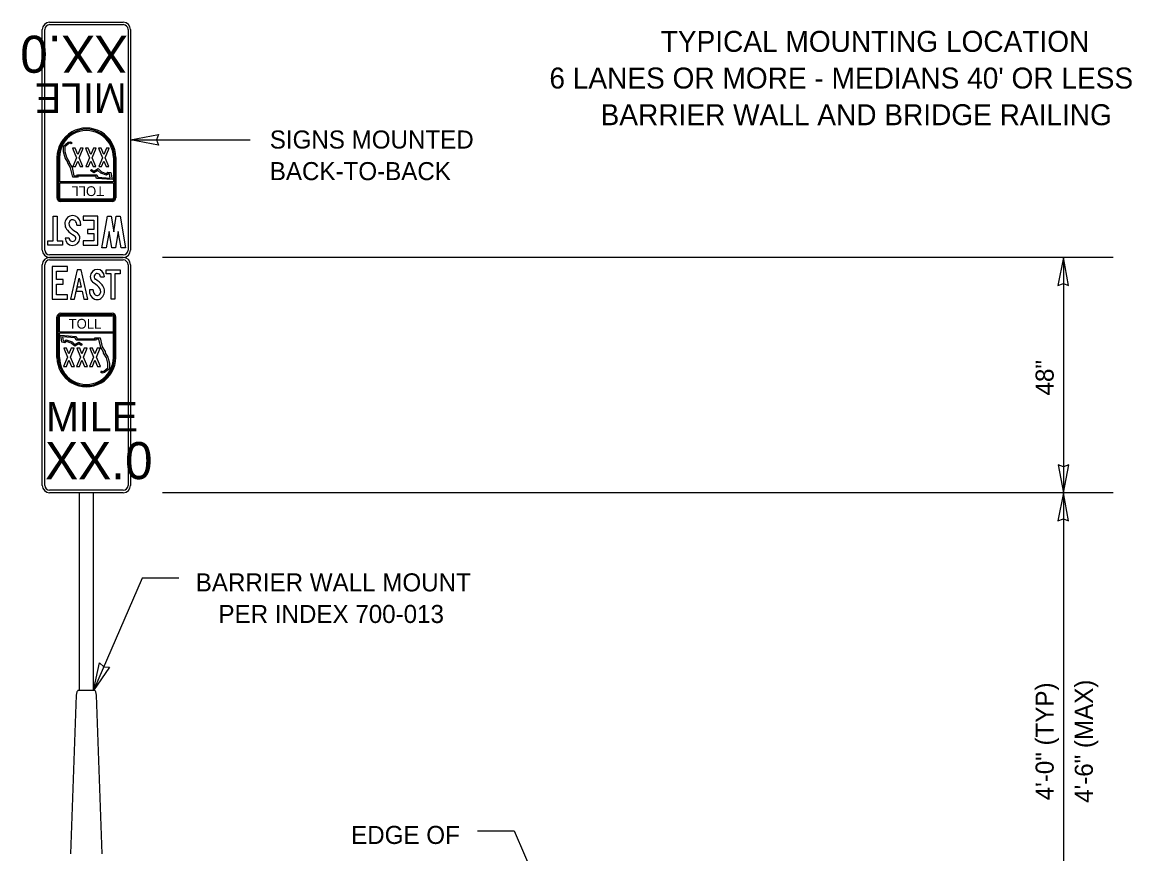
# Model space of a CAD drawing. Extents: x 57428 to 58066, y 11696 to 12105.
# Drawn here: x 57750 to 57922.1, y 11796.7 to 11925.7 of the extents above; entities that cross this region are included whole.
import ezdxf

# ---------------------------------------------------------------- set-up
doc = ezdxf.new("R2010")
doc.units = 0
for name, color, linetype in [('DimLines_dp', 7, 'Continuous'), ('NonPlottingEle_dp', 7, 'Continuous'), ('SignPanel', 7, 'Continuous'), ('TextTables', 7, 'Continuous'), ('XSGrdLine_ex', 7, 'Continuous')]:
    doc.layers.add(name, color=color, linetype=linetype)

msp = doc.modelspace()

# ---------------------------------------------------------------- linework, layer by layer
at = {"layer": 'DimLines_dp'}
for p, q in [((57766.83, 11907.47), (57771.18, 11908.31)), ((57771.18, 11908.31), (57770.85, 11907.47)), ((57766.83, 11907.47), (57785.36, 11907.47)), ((57771.18, 11906.66), (57766.83, 11907.47)), ((57770.85, 11907.47), (57771.18, 11906.66)), ((57919.19, 11889.21), (57771.8, 11889.21)), ((57911.45, 11889.21), (57910.61, 11884.86)), ((57911.45, 11889.21), (57911.45, 11852.71)), ((57912.26, 11884.86), (57911.45, 11889.21)), ((57910.61, 11884.86), (57911.45, 11885.19)), ((57911.45, 11885.19), (57912.26, 11884.86)), ((57911.45, 11858.7), (57911.45, 11772.84)), ((57911.45, 11856.73), (57910.64, 11857.06)), ((57910.64, 11857.06), (57911.45, 11852.71)), ((57911.45, 11856.73), (57910.64, 11857.06)), ((57910.64, 11857.06), (57911.45, 11852.71)), ((57911.45, 11852.71), (57912.29, 11857.06)), ((57912.29, 11857.06), (57911.45, 11856.73)), ((57911.45, 11852.71), (57912.29, 11857.06)), ((57912.29, 11857.06), (57911.45, 11856.73)), ((57919.19, 11852.71), (57771.8, 11852.71)), ((57911.45, 11852.71), (57910.61, 11848.36)), ((57912.26, 11848.36), (57911.45, 11852.71)), ((57910.61, 11848.36), (57911.45, 11848.69)), ((57911.45, 11848.69), (57912.26, 11848.36)), ((57768.66, 11839.46), (57761.07, 11822.02)), ((57774.31, 11839.46), (57768.66, 11839.46)), ((57761.07, 11822.02), (57762.04, 11826.34)), ((57763.55, 11825.68), (57761.07, 11822.02)), ((57762.04, 11826.34), (57762.68, 11825.7)), ((57762.68, 11825.7), (57763.55, 11825.68)), ((57820.64, 11800.28), (57826.29, 11800.28)), ((57826.29, 11800.28), (57839.61, 11769.66))]:
    msp.add_line(p, q, dxfattribs=at)
at = {"layer": 'NonPlottingEle_dp'}
for p, q in [((57758.91, 11822.02), (57758.91, 11852.73)), ((57761.07, 11822.02), (57761.07, 11852.73))]:
    msp.add_line(p, q, dxfattribs=at)
at = {"layer": 'SignPanel'}
for p, q in [((57756.43, 11906.48), (57757.18, 11907.09)), ((57756.43, 11905.62), (57756.43, 11906.48)), ((57757.29, 11906.88), (57756.66, 11906.37)), ((57756.66, 11906.37), (57756.66, 11905.65)), ((57757.18, 11907.09), (57757.54, 11907.18)), ((57757.49, 11906.93), (57757.29, 11906.88)), ((57757.63, 11906.83), (57757.49, 11906.93)), ((57757.54, 11907.18), (57757.77, 11907.02)), ((57757.77, 11907.02), (57757.63, 11906.83)), ((57755.43, 11904.74), (57755.43, 11898.46)), ((57755.62, 11904.74), (57755.62, 11898.46)), ((57755.81, 11904.74), (57755.81, 11900.94)), ((57756.68, 11904.69), (57756.43, 11905.62)), ((57756.66, 11905.65), (57756.9, 11904.78)), ((57757.09, 11904.02), (57756.68, 11904.69)), ((57756.9, 11904.78), (57757.32, 11904.08)), ((57764.17, 11904.74), (57764.17, 11900.94)), ((57764.36, 11904.74), (57764.36, 11898.46)), ((57764.55, 11904.74), (57764.55, 11898.46)), ((57757.09, 11903.83), (57757.09, 11904.02)), ((57757.54, 11903.11), (57757.09, 11903.83)), ((57757.32, 11904.08), (57757.32, 11903.9)), ((57757.32, 11903.9), (57757.76, 11903.2)), ((57757.88, 11901.68), (57757.54, 11903.11)), ((57757.76, 11903.2), (57758.06, 11901.91)), ((57760.65, 11902.69), (57760.78, 11902.88)), ((57760.78, 11902.88), (57761.16, 11902.62)), ((57761.16, 11902.62), (57761.79, 11903)), ((57761.79, 11903), (57762.33, 11902.5)), ((57758.61, 11901.68), (57757.88, 11901.68)), ((57758.06, 11901.91), (57758.49, 11901.91)), ((57758.49, 11901.91), (57758.59, 11902.06)), ((57758.59, 11902.06), (57761.6, 11902.06)), ((57758.71, 11901.83), (57758.61, 11901.68)), ((57761.45, 11901.83), (57758.71, 11901.83)), ((57761.15, 11902.35), (57760.65, 11902.69)), ((57761.76, 11902.71), (57761.15, 11902.35)), ((57761.58, 11901.49), (57761.45, 11901.83)), ((57763.96, 11901.3), (57761.58, 11901.49)), ((57761.6, 11902.06), (57761.74, 11901.7)), ((57761.74, 11901.7), (57763.69, 11901.55)), ((57762.21, 11902.29), (57761.76, 11902.71)), ((57763.13, 11902), (57762.21, 11902.29)), ((57762.33, 11902.5), (57763.08, 11902.25)), ((57762.7, 11901.64), (57762.7, 11901.64)), ((57763.08, 11902.25), (57763.33, 11902.45)), ((57763.4, 11902.21), (57763.13, 11902)), ((57763.33, 11902.45), (57763.79, 11902.39)), ((57763.59, 11902.18), (57763.4, 11902.21)), ((57763.69, 11901.55), (57763.59, 11902.18)), ((57763.79, 11902.39), (57763.96, 11901.3)), ((57764.17, 11900.94), (57755.81, 11900.94)), ((57755.81, 11900.74), (57755.81, 11898.46)), ((57764.17, 11900.74), (57755.81, 11900.74)), ((57764.17, 11900.74), (57764.17, 11898.46)), ((57763.98, 11898.28), (57756, 11898.28)), ((57763.98, 11898.08), (57756, 11898.08)), ((57763.98, 11897.89), (57756, 11897.89)), ((57758.49, 11894.24), (57759.12, 11894.24)), ((57758.49, 11894.24), (57759.12, 11894.24)), ((57758.49, 11894.24), (57759.12, 11894.24)), ((57757.3, 11892.23), (57756.68, 11892.23)), ((57757.3, 11892.23), (57756.68, 11892.23)), ((57757.3, 11892.23), (57756.68, 11892.23)), ((57762.18, 11886.22), (57762.77, 11886.22)), ((57762.18, 11886.22), (57762.77, 11886.22)), ((57762.18, 11886.22), (57762.77, 11886.22)), ((57761.05, 11884.18), (57760.45, 11884.18)), ((57761.05, 11884.18), (57760.45, 11884.18)), ((57761.05, 11884.18), (57760.45, 11884.18)), ((57756, 11880.56), (57763.98, 11880.56)), ((57755.43, 11873.71), (57755.43, 11879.99)), ((57755.62, 11873.71), (57755.62, 11879.99)), ((57755.81, 11877.71), (57755.81, 11879.99)), ((57756, 11880.37), (57763.98, 11880.37)), ((57756, 11880.17), (57763.98, 11880.17)), ((57764.17, 11877.71), (57764.17, 11879.99)), ((57764.36, 11873.71), (57764.36, 11879.99)), ((57764.55, 11873.71), (57764.55, 11879.99)), ((57755.81, 11877.71), (57764.17, 11877.71)), ((57755.81, 11873.71), (57755.81, 11877.52)), ((57755.81, 11877.52), (57764.17, 11877.52)), ((57756.19, 11876.06), (57756.02, 11877.15)), ((57756.02, 11877.15), (57758.4, 11876.96)), ((57764.17, 11873.71), (57764.17, 11877.52)), ((57756.65, 11876), (57756.19, 11876.06)), ((57758.24, 11876.75), (57756.29, 11876.9)), ((57756.29, 11876.9), (57756.39, 11876.27)), ((57756.39, 11876.27), (57756.58, 11876.24)), ((57756.58, 11876.24), (57756.85, 11876.46)), ((57756.9, 11876.2), (57756.65, 11876)), ((57756.85, 11876.46), (57757.77, 11876.16)), ((57757.65, 11875.95), (57756.9, 11876.2)), ((57757.28, 11876.81), (57757.28, 11876.81)), ((57758.19, 11875.45), (57757.65, 11875.95)), ((57757.77, 11876.16), (57758.22, 11875.74)), ((57758.82, 11875.83), (57758.19, 11875.45)), ((57758.22, 11875.74), (57758.83, 11876.1)), ((57758.38, 11876.39), (57758.24, 11876.75)), ((57761.39, 11876.39), (57758.38, 11876.39)), ((57758.4, 11876.96), (57758.54, 11876.62)), ((57758.54, 11876.62), (57761.27, 11876.62)), ((57759.2, 11875.57), (57758.82, 11875.83)), ((57758.83, 11876.1), (57759.33, 11875.76)), ((57759.33, 11875.76), (57759.2, 11875.57)), ((57761.27, 11876.62), (57761.37, 11876.77)), ((57761.37, 11876.77), (57762.1, 11876.77)), ((57761.49, 11876.54), (57761.39, 11876.39)), ((57761.92, 11876.54), (57761.49, 11876.54)), ((57762.22, 11875.25), (57761.92, 11876.54)), ((57762.1, 11876.77), (57762.44, 11875.34)), ((57762.44, 11875.34), (57762.89, 11874.62)), ((57762.66, 11874.55), (57762.22, 11875.25)), ((57762.66, 11874.37), (57762.66, 11874.55)), ((57763.09, 11873.67), (57762.66, 11874.37)), ((57762.89, 11874.62), (57762.89, 11874.43)), ((57762.89, 11874.43), (57763.3, 11873.76)), ((57763.32, 11872.8), (57763.09, 11873.67)), ((57763.3, 11873.76), (57763.55, 11872.84)), ((57762.69, 11871.57), (57763.32, 11872.08)), ((57763.55, 11871.97), (57762.8, 11871.36)), ((57763.32, 11872.08), (57763.32, 11872.8)), ((57763.55, 11872.84), (57763.55, 11871.97)), ((57762.22, 11871.43), (57762.35, 11871.62)), ((57762.44, 11871.27), (57762.22, 11871.43)), ((57762.35, 11871.62), (57762.49, 11871.52)), ((57762.8, 11871.36), (57762.44, 11871.27)), ((57762.49, 11871.52), (57762.69, 11871.57))]:
    msp.add_line(p, q, dxfattribs=at)
for points in [[(57754.29, 11925.72), (57765.69, 11925.72)], [(57754.29, 11925.34), (57765.69, 11925.34)], [(57753.15, 11890.37), (57753.15, 11924.58)], [(57753.53, 11890.37), (57753.53, 11924.58)], [(57766.45, 11924.58), (57766.45, 11890.37)], [(57766.83, 11924.58), (57766.83, 11890.37)], [(57765.69, 11889.61), (57754.29, 11889.61)], [(57765.69, 11889.23), (57754.29, 11889.23)], [(57754.29, 11889.23), (57765.69, 11889.23)], [(57753.15, 11853.87), (57753.15, 11888.08)], [(57753.53, 11853.87), (57753.53, 11888.08)], [(57754.29, 11888.85), (57765.69, 11888.85)], [(57766.45, 11888.08), (57766.45, 11853.87)], [(57766.83, 11888.08), (57766.83, 11853.87)], [(57765.69, 11853.11), (57754.29, 11853.11)], [(57765.69, 11852.73), (57754.29, 11852.73)]]:
    msp.add_lwpolyline(points, dxfattribs=at)
for points in [[(57759.07, 11906.16), (57758.66, 11905.18), (57758.25, 11906.16), (57757.83, 11906.16), (57758.45, 11904.67), (57757.88, 11903.31), (57758.3, 11903.31), (57758.66, 11904.16), (57759.02, 11903.31), (57759.45, 11903.31), (57758.87, 11904.67), (57759.5, 11906.16)], [(57761.09, 11906.16), (57760.68, 11905.18), (57760.27, 11906.16), (57759.84, 11906.16), (57760.46, 11904.67), (57759.89, 11903.31), (57760.32, 11903.31), (57760.68, 11904.16), (57761.04, 11903.31), (57761.46, 11903.31), (57760.89, 11904.67), (57761.51, 11906.16)], [(57763.1, 11906.16), (57762.69, 11905.18), (57762.28, 11906.16), (57761.86, 11906.16), (57762.48, 11904.67), (57761.91, 11903.31), (57762.33, 11903.31), (57762.69, 11904.16), (57763.05, 11903.31), (57763.48, 11903.31), (57762.91, 11904.67), (57763.53, 11906.16)], [(57755.44, 11891.78), (57756.26, 11891.78), (57756.26, 11891.15), (57753.99, 11891.15), (57753.99, 11891.78), (57754.82, 11891.78), (57754.82, 11895.65), (57755.44, 11895.65)], [(57755.44, 11891.78), (57756.26, 11891.78), (57756.26, 11891.15), (57753.99, 11891.15), (57753.99, 11891.78), (57754.82, 11891.78), (57754.82, 11895.65), (57755.44, 11895.65)], [(57755.44, 11891.78), (57756.26, 11891.78), (57756.26, 11891.15), (57753.99, 11891.15), (57753.99, 11891.78), (57754.82, 11891.78), (57754.82, 11895.65), (57755.44, 11895.65)], [(57761.14, 11895.02), (57761.14, 11893.58), (57760.17, 11893.58), (57760.17, 11892.95), (57761.14, 11892.95), (57761.14, 11891.78), (57759.5, 11891.78), (57759.5, 11891.15), (57761.76, 11891.15), (57761.76, 11895.65), (57759.5, 11895.65), (57759.5, 11895.02)], [(57761.14, 11895.02), (57761.14, 11893.58), (57760.17, 11893.58), (57760.17, 11892.95), (57761.14, 11892.95), (57761.14, 11891.78), (57759.5, 11891.78), (57759.5, 11891.15), (57761.76, 11891.15), (57761.76, 11895.65), (57759.5, 11895.65), (57759.5, 11895.02)], [(57761.14, 11895.02), (57761.14, 11893.58), (57760.17, 11893.58), (57760.17, 11892.95), (57761.14, 11892.95), (57761.14, 11891.78), (57759.5, 11891.78), (57759.5, 11891.15), (57761.76, 11891.15), (57761.76, 11895.65), (57759.5, 11895.65), (57759.5, 11895.02)], [(57764.93, 11893.26), (57764.52, 11890.7), (57763.92, 11890.7), (57763.51, 11893.26), (57763.06, 11890.7), (57762.37, 11890.7), (57763.24, 11895.65), (57763.83, 11895.65), (57764.22, 11893.18), (57764.61, 11895.65), (57765.2, 11895.65), (57766.07, 11890.7), (57765.38, 11890.7)], [(57764.93, 11893.26), (57764.52, 11890.7), (57763.92, 11890.7), (57763.51, 11893.26), (57763.06, 11890.7), (57762.37, 11890.7), (57763.24, 11895.65), (57763.83, 11895.65), (57764.22, 11893.18), (57764.61, 11895.65), (57765.2, 11895.65), (57766.07, 11890.7), (57765.38, 11890.7)], [(57764.93, 11893.26), (57764.52, 11890.7), (57763.92, 11890.7), (57763.51, 11893.26), (57763.06, 11890.7), (57762.37, 11890.7), (57763.24, 11895.65), (57763.83, 11895.65), (57764.22, 11893.18), (57764.61, 11895.65), (57765.2, 11895.65), (57766.07, 11890.7), (57765.38, 11890.7)], [(57755.35, 11883.45), (57755.35, 11885.07), (57756.37, 11885.07), (57756.37, 11885.78), (57755.35, 11885.78), (57755.35, 11887.1), (57757.07, 11887.1), (57757.07, 11887.81), (57754.7, 11887.81), (57754.7, 11882.74), (57757.07, 11882.74), (57757.07, 11883.45)], [(57755.35, 11883.45), (57755.35, 11885.07), (57756.37, 11885.07), (57756.37, 11885.78), (57755.35, 11885.78), (57755.35, 11887.1), (57757.07, 11887.1), (57757.07, 11887.81), (57754.7, 11887.81), (57754.7, 11882.74), (57757.07, 11882.74), (57757.07, 11883.45)], [(57755.35, 11883.45), (57755.35, 11885.07), (57756.37, 11885.07), (57756.37, 11885.78), (57755.35, 11885.78), (57755.35, 11887.1), (57757.07, 11887.1), (57757.07, 11887.81), (57754.7, 11887.81), (57754.7, 11882.74), (57757.07, 11882.74), (57757.07, 11883.45)], [(57759.32, 11883.97), (57759.59, 11882.74), (57760.2, 11882.74), (57759.18, 11887.32), (57758.55, 11887.32), (57757.53, 11882.74), (57758.13, 11882.74), (57758.41, 11883.97)], [(57758.55, 11884.61), (57758.41, 11883.97), (57759.32, 11883.97), (57759.59, 11882.74), (57760.2, 11882.74), (57759.18, 11887.32), (57758.55, 11887.32), (57757.53, 11882.74), (57758.13, 11882.74), (57758.86, 11886.02), (57759.18, 11884.61)], [(57758.55, 11884.61), (57758.41, 11883.97), (57759.32, 11883.97), (57759.59, 11882.74), (57760.2, 11882.74), (57759.18, 11887.32), (57758.55, 11887.32), (57757.53, 11882.74), (57758.13, 11882.74), (57758.86, 11886.02), (57759.18, 11884.61)], [(57763.83, 11886.68), (57763.05, 11886.68), (57763.05, 11887.32), (57765.2, 11887.32), (57765.2, 11886.68), (57764.42, 11886.68), (57764.42, 11882.74), (57763.83, 11882.74)], [(57763.83, 11886.68), (57763.05, 11886.68), (57763.05, 11887.32), (57765.2, 11887.32), (57765.2, 11886.68), (57764.42, 11886.68), (57764.42, 11882.74), (57763.83, 11882.74)], [(57763.83, 11886.68), (57763.05, 11886.68), (57763.05, 11887.32), (57765.2, 11887.32), (57765.2, 11886.68), (57764.42, 11886.68), (57764.42, 11882.74), (57763.83, 11882.74)], [(57758.86, 11886.02), (57759.18, 11884.61), (57758.55, 11884.61)], [(57756.88, 11872.29), (57757.29, 11873.27), (57757.7, 11872.29), (57758.12, 11872.29), (57757.5, 11873.78), (57758.07, 11875.14), (57757.65, 11875.14), (57757.29, 11874.29), (57756.93, 11875.14), (57756.5, 11875.14), (57757.07, 11873.78), (57756.45, 11872.29)], [(57758.9, 11872.29), (57759.3, 11873.27), (57759.71, 11872.29), (57760.14, 11872.29), (57759.52, 11873.78), (57760.09, 11875.14), (57759.66, 11875.14), (57759.3, 11874.29), (57758.95, 11875.14), (57758.52, 11875.14), (57759.09, 11873.78), (57758.47, 11872.29)], [(57760.91, 11872.29), (57761.32, 11873.27), (57761.73, 11872.29), (57762.16, 11872.29), (57761.53, 11873.78), (57762.11, 11875.14), (57761.68, 11875.14), (57761.32, 11874.29), (57760.96, 11875.14), (57760.53, 11875.14), (57761.11, 11873.78), (57760.48, 11872.29)]]:
    msp.add_lwpolyline(points, close=True, dxfattribs=at)
for centre, radius, start, end in [((57754.29, 11924.58), 1.14, 90, 180), ((57754.29, 11924.58), 0.76, 90, 180), ((57765.69, 11924.58), 1.14, 360, 90), ((57765.69, 11924.58), 0.76, 360, 90), ((57754.29, 11890.37), 1.14, 180, 270), ((57754.29, 11888.08), 1.14, 90, 180), ((57754.29, 11890.37), 0.76, 180, 270), ((57765.69, 11890.37), 1.14, 270, 360), ((57765.69, 11890.37), 0.76, 270, 360), ((57765.69, 11888.08), 1.14, 0, 90), ((57754.29, 11888.08), 0.76, 90, 180), ((57765.69, 11888.08), 0.76, 0, 90), ((57754.29, 11853.87), 1.14, 180, 270), ((57754.29, 11853.87), 0.76, 180, 270), ((57765.69, 11853.87), 1.14, 270, 360), ((57765.69, 11853.87), 0.76, 270, 360)]:
    msp.add_arc(centre, radius, start, end, dxfattribs=at)
for centre, major_axis, ratio, start_param, end_param in [((57759.99, 11904.74), (0, 4.56), 0.9997, 4.712389, 7.853982), ((57759.99, 11904.74), (0, 4.37), 0.9997, 4.712389, 7.853982), ((57759.99, 11904.74), (0, 4.18), 0.9997, 4.712389, 7.853982), ((57756, 11898.47), (0, -0.57), 0.9997, 4.712389, 6.283185), ((57756, 11898.47), (0, -0.38), 0.9997, 4.712389, 6.283185), ((57756, 11898.47), (0, -0.19), 0.9997, 4.712389, 6.283185), ((57763.98, 11898.47), (0, -0.38), 0.9997, 0, 1.570796), ((57763.98, 11898.47), (0, -0.19), 0.9997, 0, 1.570796), ((57763.98, 11898.47), (0, -0.57), 0.9997, 0, 1.570796), ((57758.03, 11894.43), (0, -1.4), 0.981197, 4.260987, 5.485755), ((57758.03, 11894.43), (0, -1.4), 0.981197, 4.260987, 5.485755), ((57758.03, 11894.43), (0, -1.4), 0.981197, 4.260987, 5.485755), ((57757.87, 11894.49), (0, -1.23), 0.981197, 2.786047, 4.251692), ((57757.87, 11894.49), (0, -1.23), 0.981197, 2.786047, 4.251692), ((57757.87, 11894.49), (0, -1.23), 0.981197, 2.786047, 4.251692), ((57758.04, 11894.42), (0, -0.78), 0.981197, 4.254409, 5.632398), ((57758.04, 11894.42), (0, -0.78), 0.981197, 4.254409, 5.632398), ((57758.04, 11894.42), (0, -0.78), 0.981197, 4.254409, 5.632398), ((57757.85, 11894.5), (0, -0.572), 0.981197, 2.261787, 4.23006), ((57757.85, 11894.5), (0, -0.572), 0.981197, 2.261787, 4.23006), ((57757.85, 11894.5), (0, -0.572), 0.981197, 2.261787, 4.23006), ((57757.61, 11894.28), (0, -0.897), 0.981197, 1.524757, 2.28214), ((57757.61, 11894.28), (0, -0.897), 0.981197, 1.524757, 2.28214), ((57757.61, 11894.28), (0, -0.897), 0.981197, 1.524757, 2.28214), ((57757.67, 11894.31), (0, -1.47), 0.981197, 1.526364, 2.701682), ((57757.67, 11894.31), (0, -1.47), 0.981197, 1.526364, 2.701682), ((57757.67, 11894.31), (0, -1.47), 0.981197, 1.526364, 2.701682), ((57760.15, 11896.4), (0, -4.32), 0.981197, 5.462886, 5.782242), ((57760.15, 11896.4), (0, -4.32), 0.981197, 5.462886, 5.782242), ((57760.15, 11896.4), (0, -4.32), 0.981197, 5.462886, 5.782242), ((57760.68, 11897.09), (0, -4.56), 0.981197, 5.515137, 5.786988), ((57760.68, 11897.09), (0, -4.56), 0.981197, 5.515137, 5.786988), ((57760.68, 11897.09), (0, -4.56), 0.981197, 5.515137, 5.786988), ((57757.9, 11892.21), (0, -0.453), 0.981197, 0.87378, 2.656959), ((57757.9, 11892.21), (0, -0.453), 0.981197, 0.87378, 2.656959), ((57757.9, 11892.21), (0, -0.453), 0.981197, 0.87378, 2.656959), ((57757.94, 11892.23), (0, -1.05), 0.981197, 1.534831, 2.511766), ((57757.94, 11892.23), (0, -1.05), 0.981197, 1.534831, 2.511766), ((57757.94, 11892.23), (0, -1.05), 0.981197, 1.534831, 2.511766), ((57757.83, 11892.26), (0, -1.17), 0.981197, 4.736267, 7.790596), ((57757.83, 11892.26), (0, -1.17), 0.981197, 4.736267, 7.790596), ((57757.83, 11892.26), (0, -1.17), 0.981197, 4.736267, 7.790596), ((57757.84, 11892.27), (0, -0.55), 0.981197, 4.786904, 7.140738), ((57757.84, 11892.27), (0, -0.55), 0.981197, 4.786904, 7.140738), ((57757.84, 11892.27), (0, -0.55), 0.981197, 4.786904, 7.140738), ((57761.68, 11886.19), (0, 1.19), 0.91923, 4.736267, 7.790596), ((57761.68, 11886.19), (0, 1.19), 0.91923, 4.736267, 7.790596), ((57761.68, 11886.19), (0, 1.19), 0.91923, 4.736267, 7.790596), ((57761.57, 11886.23), (0, 1.07), 0.91923, 1.534831, 2.511766), ((57761.57, 11886.23), (0, 1.07), 0.91923, 1.534831, 2.511766), ((57761.57, 11886.23), (0, 1.07), 0.91923, 1.534831, 2.511766), ((57761.61, 11886.25), (0, 0.46), 0.91923, 0.87378, 2.656959), ((57761.61, 11886.25), (0, 0.46), 0.91923, 0.87378, 2.656959), ((57761.61, 11886.25), (0, 0.46), 0.91923, 0.87378, 2.656959), ((57761.67, 11886.18), (0, 0.558), 0.91923, 4.786904, 7.140738), ((57761.67, 11886.18), (0, 0.558), 0.91923, 4.786904, 7.140738), ((57761.67, 11886.18), (0, 0.558), 0.91923, 4.786904, 7.140738), ((57759.47, 11881.99), (0, 4.39), 0.91923, 5.462886, 5.782242), ((57759.47, 11881.99), (0, 4.39), 0.91923, 5.462886, 5.782242), ((57759.47, 11881.99), (0, 4.39), 0.91923, 5.462886, 5.782242), ((57761.83, 11884.11), (0, 1.5), 0.91923, 1.526364, 2.701682), ((57761.83, 11884.11), (0, 1.5), 0.91923, 1.526364, 2.701682), ((57761.83, 11884.11), (0, 1.5), 0.91923, 1.526364, 2.701682), ((57758.96, 11881.29), (0, 4.63), 0.91923, 5.515137, 5.786988), ((57758.96, 11881.29), (0, 4.63), 0.91923, 5.515137, 5.786988), ((57758.96, 11881.29), (0, 4.63), 0.91923, 5.515137, 5.786988), ((57761.88, 11884.14), (0, 0.911), 0.91923, 1.524757, 2.28214), ((57761.88, 11884.14), (0, 0.911), 0.91923, 1.524757, 2.28214), ((57761.88, 11884.14), (0, 0.911), 0.91923, 1.524757, 2.28214), ((57761.48, 11883.99), (0, 0.792), 0.91923, 4.254409, 5.632398), ((57761.48, 11883.99), (0, 0.792), 0.91923, 4.254409, 5.632398), ((57761.48, 11883.99), (0, 0.792), 0.91923, 4.254409, 5.632398), ((57761.49, 11883.99), (0, 1.42), 0.91923, 4.260987, 5.485755), ((57761.49, 11883.99), (0, 1.42), 0.91923, 4.260987, 5.485755), ((57761.49, 11883.99), (0, 1.42), 0.91923, 4.260987, 5.485755), ((57761.64, 11883.93), (0, 1.24), 0.91923, 2.786047, 4.251692), ((57761.64, 11883.93), (0, 1.24), 0.91923, 2.786047, 4.251692), ((57761.64, 11883.93), (0, 1.24), 0.91923, 2.786047, 4.251692), ((57761.66, 11883.91), (0, 0.581), 0.91923, 2.261787, 4.23006), ((57761.66, 11883.91), (0, 0.581), 0.91923, 2.261787, 4.23006), ((57761.66, 11883.91), (0, 0.581), 0.91923, 2.261787, 4.23006), ((57756, 11879.99), (0, 0.57), 0.9997, 0, 1.570796), ((57763.98, 11879.99), (0, 0.57), 0.9997, 4.712389, 6.283185), ((57756, 11879.99), (0, 0.38), 0.9997, 0, 1.570796), ((57756, 11879.99), (0, 0.19), 0.9997, 0, 1.570796), ((57763.98, 11879.99), (0, 0.38), 0.9997, 4.712389, 6.283185), ((57763.98, 11879.99), (0, 0.19), 0.9997, 4.712389, 6.283185), ((57759.99, 11873.71), (0, -4.56), 0.9997, 4.712389, 7.853982), ((57759.99, 11873.71), (0, -4.37), 0.9997, 4.712389, 7.853982), ((57759.99, 11873.71), (0, -4.18), 0.9997, 4.712389, 7.853982)]:
    msp.add_ellipse(centre, major_axis=major_axis, ratio=ratio, start_param=start_param, end_param=end_param, dxfattribs=at)
at = {"layer": 'XSGrdLine_ex'}
for p, q in [((57761.3, 11822.02), (57758.68, 11822.02)), ((57757.56, 11796.71), (57758.43, 11821.33)), ((57762.42, 11796.71), (57761.56, 11821.33))]:
    msp.add_line(p, q, dxfattribs=at)
for centre, start_param, end_param in [((57758.68, 11821.25), 0, 1.465919), ((57761.3, 11821.25), 4.817266, 6.283185)]:
    msp.add_ellipse(centre, major_axis=(0, 0.77), ratio=0.333333, start_param=start_param, end_param=end_param, dxfattribs=at)

# ---------------------------------------------------------------- texts
at = {"layer": 'DimLines_dp'}
for s, p in [('SIGNS MOUNTED', (57788.42, 11906.12)), ('BACK-TO-BACK', (57788.42, 11901.22)), ('BARRIER WALL MOUNT', (57776.94, 11837.42)), ('PER INDEX 700-013', (57780.46, 11832.52)), ('EDGE OF ', (57801.03, 11798.24))]:
    msp.add_text(s, height=2.8, dxfattribs=at).set_placement(p)
for s, p in [('48"', (57909.95, 11867.82)), ('4\'-0" (TYP)', (57909.95, 11805.02)), ('4\'-6" (MAX)', (57916.03, 11804.62))]:
    msp.add_text(s, height=2.8, rotation=90, dxfattribs=at).set_placement(p)
at = {"layer": 'SignPanel'}
for s, height, rotation, p in [('XX.0', 5.75, 180, (57766.4, 11923.63)), ('MILE', 4.562, 180, (57766.24, 11916.22)), ('TOLL', 1.519, 180, (57762.75, 11900.27)), ('TOLL', 1.519, 360, (57757.23, 11878.18)), ('MILE', 4.562, 360, (57753.74, 11862.23)), ('XX.0', 5.75, 360, (57753.58, 11854.83))]:
    msp.add_text(s, height=height, rotation=rotation, dxfattribs=at).set_placement(p)
at = {"layer": 'TextTables'}
for s, p in [('TYPICAL MOUNTING LOCATION', (57849.03, 11921.12)), ("6 LANES OR MORE - MEDIANS 40' OR LESS", (57831.77, 11915.43)), ('BARRIER WALL AND BRIDGE RAILING', (57839.71, 11909.74))]:
    msp.add_text(s, height=3.2524, dxfattribs=at).set_placement(p)

doc.saveas('drawing.dxf')
